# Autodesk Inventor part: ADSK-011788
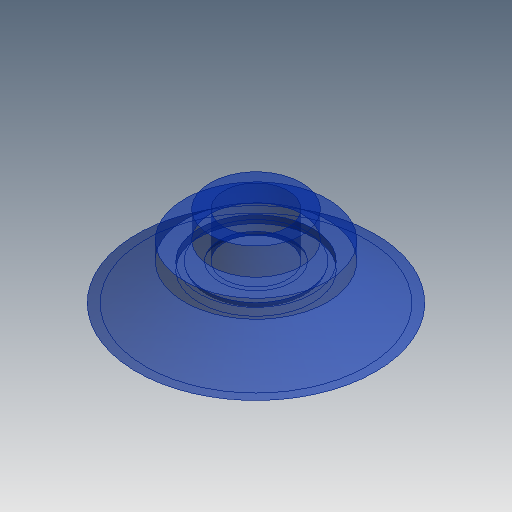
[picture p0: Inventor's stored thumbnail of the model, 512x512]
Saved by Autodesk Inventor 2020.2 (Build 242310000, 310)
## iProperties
Created: 1999-11
Part Number: ADSK-011788
Document SubType Name: Modeling
Designer: sspink
Material: Générique
Density: 1 g/cm^3
Appearance: Blue(Clear)
Mass: 3.60416 g
Surface Area: 37.8067 cm^2
Volume: 3.60416 cm^3
Control State: 0
Checked Out: False
Last Check In By: sspink
Master: False
Shininess: 0.0
Length Units: 11272
Angle Units: 11279
Time Units: 11290
Mass Units: 11286
Length Display Precision: 3
Angle Display Precision: 2
Compacted: True
Dimensions: 0,6x1,6x1,6 in
Mass: 0,008 lb
VLT_Material: Generic
Density: 0.0
Volumn: 0.0
Area: 0.0
PropertySet Name: Model Information
Author: sspink
Revision Number: -
Title: ADSK-011788
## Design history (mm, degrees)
node "Revolution1" dims "d13" = 90 deg
node "Hole1" dims "d14" = 11.0998, "d15" = 9.525, "d16" = 6.35, "d17" = 60 deg, "d18" = 19.05, "d19" = 118 deg
workaxis "Work Axis1"
workplane "Work Plane1"
workplane "Work Plane3"
node "Solide1"
node "Corps solides"
node "Corps surfaciques"
sketch "Sketch1"
  geometry: L1 (10.005, 7.858)-(10.005, -0.016) reference; L2 (10.005, -0.016)-(16.355, -0.016); L3 (29.246, -6.366)-(30.833, -6.366); L4 (30.833, -6.366)-(22.451, -0.018); L5 (22.451, -0.018)-(22.451, 3.157); L6 (22.451, 3.157)-(17.943, 3.157) reference; L7 (17.943, 3.157)-(17.943, 7.858); L8 (17.943, 7.858)-(10.005, 7.858) reference; L9 (18.895, -0.016)-(19.911, -0.016); L10 (19.911, -0.016)-(19.911, -1.363); L11 (19.911, -1.363)-(29.246, -6.366); A1 r 1.27 centre (17.625, -0.016) between (16.355, -0.016) and (18.895, -0.016)
  constraints: 22 end point, 3 perpendicular, 2 horizontal, 2 parallel, 2 point on circle, 2 vertical, 1 centre point
  dimensions: "d0" = 6.35 distance of L1.end L2.end; "d1" = 20.828 distance from line of L3.end L1; "d2" = 1.27 radius of A1; "d5" = 1.5875 distance of L3.start L3.end; "d6" = 7.9375 distance of L7.end L1.start; "d7" = 12.446 distance between parallel lines of L5 L1; "d9" = 9.906 distance from line of L10 L1.end; "d10" = 14.224 distance between parallel lines of L3 L8; "d11" = 6.35 distance between parallel lines of L3 L2; "d12" = 3.175 distance of L4.end L5.end; "d23" = 10.59045 distance of L10.end L3.start; "d24" = 7.62 distance from line of L1 A1.centre
sketch "Sketch2"
  geometry: C1 r 7.937 at (0, 0) reference; 1 further point
  constraints: 1 coincident
other parameters: "d20" = 0, "d22" = 0
